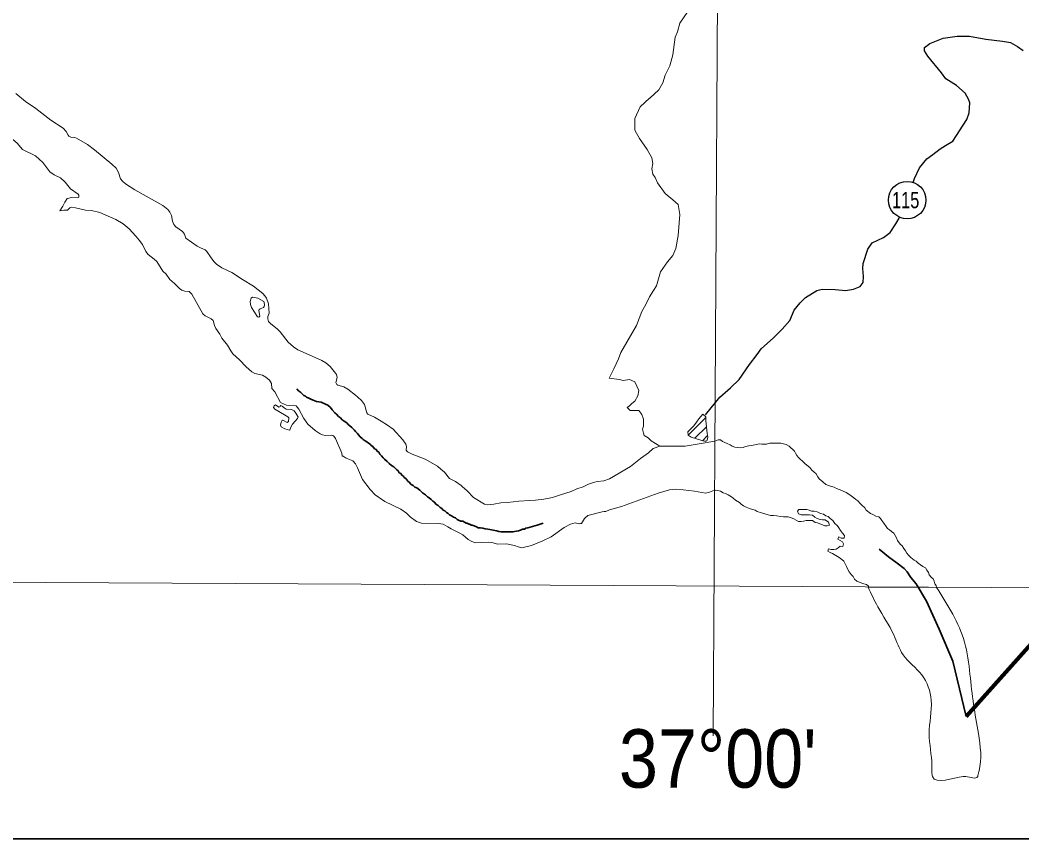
# Model space of a CAD drawing. Extents: x 553962 to 842807, y 8883888 to 9032388.
# Drawn here: x 604536 to 608828, y 8897728 to 8901238 of the extents above; entities that cross this region are included whole.
import ezdxf
from ezdxf.enums import TextEntityAlignment as Align

# ---------------------------------------------------------------- set-up
doc = ezdxf.new("R2010")
doc.units = 0
doc.header["$LTSCALE"] = 160
doc.linetypes.add('LONG_DASH_SHORT_DASH', pattern=[9.9, 6, -1.2, 1.5, -1.2])
doc.layers.add('6', color=7, linetype='Continuous', lineweight=13)

msp = doc.modelspace()

# ---------------------------------------------------------------- linework, layer by layer
at = {"layer": '6'}
for p, q in [((607398.2, 8899458.9), (607473.3, 8899534)), ((607427.1, 8899445.4), (607476, 8899494.2)), ((607458.9, 8899434.7), (607481.1, 8899456.9)), ((608462.4, 8898805.8), (608169.4, 8898807.8))]:
    msp.add_line(p, q, dxfattribs=at)
at = {"layer": '6', "lineweight": 35}
msp.add_lwpolyline([(576104.8, 8927170.9), (624533.7, 8927170.9), (624533.7, 8897728.1), (576104.8, 8897728.1)], close=True, dxfattribs=at)
at = {"layer": '6'}
for points in [[(607657.7, 8924743.3), (607574.2, 8909874.9), (607505, 8898170.6)], [(607518.6, 8901403.9), (607482.1, 8901370.7), (607412.3, 8901297.6), (607362.4, 8901224.5), (607352.5, 8901188), (607342.5, 8901164.7), (607332.5, 8901088.4), (607319.2, 8901041.9), (607299.3, 8901002), (607289.3, 8900968.8), (607272.7, 8900938.9), (607233.9, 8900903.3)], [(604517.3, 8900922.7), (604558.5, 8900888.9), (604603.8, 8900858.4), (604667, 8900809.4), (604720.7, 8900774.8), (604733.1, 8900760.8), (604741.5, 8900744.4), (604745.2, 8900740.3), (604753.2, 8900735.9), (604770.9, 8900734.2), (604776.8, 8900732.2), (604824.3, 8900704.6), (604854.7, 8900681.5), (604929.1, 8900620.1), (604947.7, 8900602.6), (604957.6, 8900585), (604966.3, 8900557.4), (604974.2, 8900547), (604987.4, 8900535.9), (605027.8, 8900510.6), (605147.2, 8900442.4), (605169.2, 8900426.4), (605178, 8900414.5), (605184.6, 8900400), (605189.5, 8900375.3), (605194.2, 8900361.7), (605203.3, 8900351.7), (605231.7, 8900331.2), (605239.8, 8900319.8), (605246.1, 8900303.3), (605294.8, 8900269.1), (605308.7, 8900261.3), (605318.4, 8900257.2)], [(607232.8, 8900902.4), (607193, 8900865.8), (607169.7, 8900816), (607169.7, 8900766.2), (607189.6, 8900729.7), (607222.9, 8900683.2), (607242.8, 8900646.7), (607246.1, 8900623.4), (607242.8, 8900600.2), (607246.1, 8900576.9), (607256.1, 8900563.6), (607266.1, 8900540.4), (607299.3, 8900493.9), (607332.5, 8900467.3), (607355.8, 8900447.4), (607362.4, 8900404.2), (607355.8, 8900314.6), (607345.8, 8900258.1), (607332.5, 8900228.2), (607309.3, 8900201.6), (607279.4, 8900158.5), (607262.7, 8900098.7), (607249.5, 8900078.8), (607232.8, 8900052.2), (607216.2, 8900019), (607199.6, 8899989.1), (607176.3, 8899929.3), (607109.9, 8899813.1), (607099.9, 8899786.5), (607080, 8899743.3), (607060, 8899703.5), (607103.2, 8899696.8), (607119.8, 8899693.5), (607146.4, 8899696.8), (607169.7, 8899686.9), (607186.3, 8899650.3), (607183, 8899627.1), (607169.7, 8899603.8), (607156.4, 8899593.9), (607146.4, 8899583.9), (607136.5, 8899577.3), (607149.8, 8899564), (607186.3, 8899564), (607199.6, 8899547.4), (607206.2, 8899527.4), (607206.2, 8899507.5), (607206.2, 8899497.6), (607202.9, 8899484.3), (607206.2, 8899467.7), (607209.6, 8899457.7), (607226.2, 8899447.8), (607239.5, 8899434.5), (607276, 8899411.2)], [(604545.7, 8900683.2), (604522.7, 8900710.9), (604449.6, 8900771.1), (604366, 8900847)], [(604745.3, 8900474.6), (604755.6, 8900477.1), (604782.2, 8900475.7), (604787.1, 8900478.4), (604787.9, 8900487.3), (604784.5, 8900492.2), (604752, 8900515.1), (604729.6, 8900542.8), (604709.4, 8900561), (604681.6, 8900575), (604663.6, 8900587.3), (604633.8, 8900627.5), (604602, 8900655.7), (604545.7, 8900683.2)], [(604729.9, 8900461.2), (604737.9, 8900472.8), (604745.3, 8900474.6)], [(604706.6, 8900419.8), (604719.1, 8900439.6), (604727.3, 8900457.6), (604729.9, 8900461.2), (604729.9, 8900461.2)], [(605045.3, 8900294.2), (605031, 8900312.3), (605003.2, 8900342.6), (604977.4, 8900365.2), (604945.5, 8900383.7), (604877.4, 8900413.4), (604842.3, 8900421.4), (604815.8, 8900423.5), (604773.8, 8900433.3), (604754.4, 8900435.3), (604749.3, 8900433), (604738.7, 8900423.7), (604723, 8900423.6), (604706.6, 8900419.8)], [(605438.8, 8899820.5), (605424.5, 8899844.7), (605400.3, 8899874.5), (605391.9, 8899891.1), (605374.3, 8899916.5), (605368.7, 8899929), (605362.7, 8899950.1), (605355.1, 8899957.3), (605329.3, 8899970.5), (605318.8, 8899978.5), (605271.5, 8900063.6), (605260.1, 8900073.8), (605241.3, 8900075.8), (605228.1, 8900080.5), (605218.7, 8900087.6), (605197.7, 8900109.2), (605177.8, 8900125.6), (605161.6, 8900148.5), (605147.3, 8900162.1), (605121.1, 8900202.5), (605110.9, 8900213.2), (605084.9, 8900233.7), (605074.1, 8900246.2), (605060.1, 8900275.4), (605045.3, 8900294.2)], [(605318.4, 8900257.2), (605328.1, 8900253.2), (605335.8, 8900246.2), (605350.9, 8900222.8), (605366.1, 8900202.7), (605377.3, 8900192.3), (605399.9, 8900175.6), (605442.3, 8900156.2), (605489.3, 8900126.6)], [(605489.3, 8900126.6), (605536.4, 8900097), (605576.3, 8900065.9), (605584, 8900055.8)], [(605584, 8900055.8), (605591.8, 8900045.6), (605599.5, 8900021.8), (605601.3, 8900001.9)], [(605601.3, 8900001.9), (605603.1, 8899982.1), (605597.9, 8899967.5), (605596.6, 8899957), (605600.2, 8899946.1), (605609.6, 8899935.7), (605637, 8899914.4), (605637, 8899914.4), (605649.8, 8899902), (605684.5, 8899857.5), (605707.9, 8899837.1), (605725.2, 8899825.1), (605748.8, 8899814.5)], [(605651.9, 8899599.2), (605627.2, 8899644.2), (605614.9, 8899659.3), (605613, 8899680), (605604.8, 8899694.2), (605588.8, 8899707.8), (605573.8, 8899716.3), (605540.9, 8899723.1), (605528.7, 8899729.8), (605504.9, 8899751.3), (605476.1, 8899781.6), (605446.9, 8899806.9), (605438.8, 8899820.5)], [(605748.8, 8899814.5), (605828.9, 8899778.6), (605845.6, 8899768.4), (605864.6, 8899753.2), (605875.9, 8899739.1)], [(605875.9, 8899739.1), (605887.1, 8899725), (605890.8, 8899718.1), (605893.6, 8899706.3), (605887.9, 8899684.9), (605892.5, 8899676.5), (605897.1, 8899672.9), (605922.3, 8899665.2), (605940.2, 8899656.1), (605972.7, 8899630.7), (605982.6, 8899621.7)], [(605982.6, 8899621.7), (605997.9, 8899607.7), (606011.1, 8899590.2), (606021.8, 8899555.1), (606026.3, 8899548.7), (606053.9, 8899535.2), (606082.6, 8899518.2)], [(605800.4, 8899478.3), (605768.7, 8899506.2), (605752.1, 8899530.8), (605730.5, 8899570.1), (605719.2, 8899583.9), (605706, 8899587.4), (605690.9, 8899586.3), (605677.8, 8899587.4), (605651.9, 8899599.2)], [(606082.6, 8899518.2), (606110.4, 8899501.7), (606133.8, 8899485.1), (606175, 8899438.1), (606188.2, 8899420.1), (606191.5, 8899410.3), (606189.5, 8899394.8), (606194.9, 8899386.7), (606215.6, 8899376.8), (606270.9, 8899356.2), (606324.1, 8899326.3), (606339, 8899313.3)], [(605886.8, 8899444.2), (605880.5, 8899454.1), (605875.6, 8899458), (605871.8, 8899459), (605843.6, 8899457.8), (605831.8, 8899459.6), (605821.4, 8899464.6), (605800.4, 8899478.3)], [(606167, 8899141.3), (606097.8, 8899173.8), (606057.4, 8899203.2), (606036.3, 8899225.7), (606003.4, 8899268.5), (605982, 8899319.3), (605972.7, 8899335.8), (605960.9, 8899348.2), (605932.8, 8899360.8), (605920.3, 8899368.7), (605916, 8899369.4), (605914.2, 8899381.2), (605886.8, 8899444.2)], [(606996.3, 8899256.7), (607009.1, 8899260.5), (607037.2, 8899263), (607061.2, 8899271.7), (607150.5, 8899324.7), (607193.7, 8899358.8), (607228.5, 8899383), (607248.7, 8899401.6), (607276, 8899411.2), (607305.9, 8899411.2), (607385.7, 8899411.2), (607445.5, 8899421.2), (607512.3, 8899432.5)], [(607512.3, 8899432.5), (607525.9, 8899438.3), (607537.1, 8899438.2), (607545.2, 8899432.1), (607555.3, 8899427.9), (607565.5, 8899422.8), (607577.6, 8899416.6), (607586.8, 8899411.4), (607597.9, 8899407.3), (607609.1, 8899406.2), (607621.3, 8899405.1), (607633.5, 8899406), (607643.7, 8899410), (607658, 8899413), (607671.2, 8899413.9), (607701.8, 8899420.9), (607713, 8899420.8), (607723.1, 8899420.7), (607734.3, 8899420.7), (607747.6, 8899424.6), (607757.7, 8899424.6), (607770, 8899424.5), (607783.2, 8899424.4), (607795.4, 8899424.3), (607806.6, 8899422.2), (607817.7, 8899418.1), (607830.9, 8899411.9), (607838, 8899404.7), (607846.1, 8899397.5), (607853.1, 8899390.3)], [(607853.1, 8899390.3), (607858.2, 8899381.2), (607863.2, 8899371.9), (607871.3, 8899363.7), (607878.3, 8899355.6), (607887.4, 8899347.3), (607899.6, 8899336.1), (607919.8, 8899319.6), (607927.8, 8899309.4), (607937, 8899302.2), (607946, 8899293), (607954.1, 8899280.7), (607959.1, 8899271.5), (607975.3, 8899258.1), (607987.4, 8899247.9), (607998.6, 8899242.7), (608011.8, 8899238.6), (608023, 8899235.4), (608033.1, 8899230.3), (608045.3, 8899226.1), (608056.4, 8899222), (608065.6, 8899217.8), (608075.7, 8899212.7), (608085.8, 8899205.5), (608097, 8899199.3), (608108.1, 8899190.1), (608116.2, 8899182.9), (608124.3, 8899176.7), (608135.4, 8899166.4), (608142.5, 8899159.3), (608154.6, 8899148), (608160.6, 8899137.8), (608178.8, 8899123.4), (608189, 8899119.2), (608202.2, 8899112), (608214.3, 8899108.9), (608222.4, 8899101.7), (608228.5, 8899092.5), (608236.5, 8899081.2), (608246.6, 8899067.9), (608252.7, 8899058.7), (608260.8, 8899052.6), (608269.9, 8899046.4), (608279, 8899038.2), (608291, 8899018.7), (608295, 8899007.5), (608306.1, 8898992.2), (608314.2, 8898985), (608322.3, 8898973.7), (608329.3, 8898963.5), (608335.3, 8898953.3), (608342.4, 8898945.1), (608352.5, 8898933.8), (608365.7, 8898923.5), (608374.8, 8898918.4), (608383.9, 8898910.2), (608393, 8898903), (608403.1, 8898895.8), (608414.2, 8898889.6), (608421.3, 8898880.4), (608427.3, 8898870.2), (608430.3, 8898859.9), (608439.4, 8898850.7), (608447.5, 8898843.5), (608451.5, 8898832.3)], [(606339, 8899313.3), (606353.8, 8899300.2), (606375.8, 8899273.6), (606401.3, 8899259.5), (606425.6, 8899243.5), (606430.3, 8899239.2)], [(606430.3, 8899239.2), (606451.1, 8899220.5), (606477.9, 8899191.6), (606526.1, 8899162.9), (606538.8, 8899160.4), (606552.3, 8899160.9), (606564.8, 8899163.4)], [(606850.9, 8899202.7), (606897.3, 8899217.3), (606921.3, 8899228.2), (606948.9, 8899237.7), (606970.8, 8899249.3), (606996.3, 8899256.7)], [(606743.5, 8899180.8), (606780.2, 8899185.1), (606817.4, 8899192.1), (606850.9, 8899202.7)], [(607510.3, 8899223.4), (607489.5, 8899213.8), (607472.3, 8899210.6), (607425.7, 8899218.6), (607376, 8899224.9), (607343.2, 8899226.9), (607318.7, 8899223.8), (607269.6, 8899209.6), (607112, 8899153.1), (607061.6, 8899139.4), (607044.9, 8899132.1), (607038.2, 8899131.2)], [(607965.2, 8899123.7), (607951, 8899129.9), (607937.8, 8899133.1), (607926.6, 8899133.2), (607916.5, 8899137.3), (607906.3, 8899140.4), (607892.1, 8899140.5), (607872.8, 8899140.6), (607866.6, 8899132.5), (607870.6, 8899122.3), (607882.8, 8899117.1), (607894, 8899117.1), (607904.2, 8899117), (607917.4, 8899116.9), (607930.6, 8899115.8), (607940.7, 8899107.6), (607950.8, 8899101.4), (607963, 8899097.3), (607974.2, 8899096.2), (607984.4, 8899096.1), (607999.6, 8899085.8), (608003.5, 8899073.6), (607993.3, 8899070.6), (607983.2, 8899070.6), (607973, 8899074.8), (607961.9, 8899078.9), (607952.7, 8899083.1), (607941.6, 8899084.2), (607930.4, 8899092.4), (607917.2, 8899093.5), (607903, 8899092.6), (607892.8, 8899089.6), (607881.6, 8899088.6), (607870.4, 8899088.7), (607861.3, 8899093.8), (607850.1, 8899100), (607840, 8899104.2), (607826.8, 8899108.3), (607816.6, 8899108.4), (607806.4, 8899108.4), (607793.2, 8899109.6), (607778, 8899112.7), (607763.7, 8899113.8), (607751.5, 8899113.9), (607741.4, 8899118), (607727.2, 8899122.2), (607712, 8899125.3), (607693.7, 8899131.6), (607684.6, 8899136.7), (607674.4, 8899139.9), (607661.2, 8899144), (607646, 8899150.2), (607634.8, 8899155.4), (607625.7, 8899163.6), (607617.7, 8899170.8), (607600.4, 8899180.1), (607591.3, 8899188.3), (607583.2, 8899194.4), (607569.1, 8899203.7), (607557.9, 8899208.9), (607547.8, 8899212), (607536.6, 8899218.2), (607525.4, 8899222.3), (607515.3, 8899222.4), (607510.3, 8899223.4)], [(606564.8, 8899163.4), (606594.8, 8899169.2), (606624, 8899170.2), (606673, 8899176.3), (606719.7, 8899178.1), (606743.5, 8899180.8)], [(606368.4, 8899065.7), (606348.9, 8899077), (606329, 8899080.2), (606255.6, 8899080.9), (606233.8, 8899088.8), (606207, 8899108.8), (606191.6, 8899125.1), (606167, 8899141.3)], [(607038.2, 8899131.2), (607030.1, 8899130.2), (606968.5, 8899113.9), (606953.5, 8899101.6), (606940.8, 8899080.5), (606936.9, 8899079.8)], [(608076.6, 8898895.8), (608072.6, 8898905), (608064.5, 8898918.3), (608056.4, 8898925.5), (608045.3, 8898934.7), (608031.1, 8898943), (608015.9, 8898952.2), (608006.8, 8898956.4), (607996.7, 8898961.5), (607999.8, 8898971.7), (608011, 8898968.6), (608022.1, 8898968.5), (608032.3, 8898969.5), (608040.5, 8898976.5), (608048.7, 8898982.6), (608060.9, 8898981.5), (608064, 8898992.7), (608059, 8899001.9), (608048.8, 8899007.1), (608039.7, 8899013.2), (608043.9, 8899022.4), (608054, 8899017.2), (608066.2, 8899017.1), (608067.3, 8899029.3), (608059.2, 8899038.6), (608051.2, 8899049.8), (608044.1, 8899061.1), (608036.1, 8899072.3), (608027, 8899080.5), (608017.9, 8899092.8), (608005.8, 8899102.1), (607997.7, 8899110.3), (607987.5, 8899113.4), (607977.4, 8899119.6), (607965.2, 8899123.7)], [(606669.7, 8898980.5), (606654.6, 8898985.8), (606620, 8898992.5), (606583.1, 8898992.2), (606556.5, 8898999.1), (606542.7, 8899000.4), (606485.3, 8898997.2), (606468.8, 8899003.8), (606455.3, 8899011.8), (606432, 8899031.1), (606419.7, 8899039.2), (606382.7, 8899057.4), (606368.4, 8899065.7)], [(606936.9, 8899079.8), (606931.9, 8899079.1), (606913.4, 8899083.4), (606894.4, 8899077.1), (606866.6, 8899063), (606810.7, 8899023.7), (606776, 8899005.8), (606726.3, 8898985.3), (606684.8, 8898975.2), (606669.7, 8898980.5)], [(577181.5, 8898943.8), (596544.3, 8898870.4), (623547.8, 8898727.2)], [(608169.4, 8898807.8), (608170.6, 8898811.7), (608162.5, 8898818.9), (608151.3, 8898821), (608142.2, 8898825.1), (608132.1, 8898829.2), (608120.9, 8898833.4), (608110.8, 8898841.6), (608104.8, 8898852.9), (608096.7, 8898862.1), (608087.6, 8898873.3), (608081.6, 8898882.6), (608076.6, 8898895.8)], [(608451.5, 8898832.3), (608454.5, 8898822.1), (608460.5, 8898813.9), (608462.4, 8898805.8), (608169.4, 8898807.8)]]:
    msp.add_lwpolyline(points, dxfattribs=at)
at = {"layer": '6', "lineweight": 25}
for points in [[(608362.5, 8900541.9), (608368.2, 8900558.4), (608389.8, 8900605.2), (608420.5, 8900642.9), (608446, 8900662.2), (608477.7, 8900686.6), (608500.2, 8900699.8), (608531.8, 8900719.1), (608592.3, 8900811.7), (608601.6, 8900840.2), (608604.8, 8900883), (608599.7, 8900899.3), (608584.6, 8900924.8), (608548, 8900957.4), (608502.2, 8900986.1), (608484, 8901011.6), (608424.2, 8901083), (608411, 8901106.4), (608410, 8901120.7), (608433.5, 8901137), (608490.7, 8901160.3), (608550.8, 8901168.3), (608602.8, 8901168.2), (608674, 8901155.9), (608745.3, 8901147.6), (608778.9, 8901141.4), (608808.4, 8901124), (608833.8, 8901107.7)], [(607472.2, 8899545.8), (607534.4, 8899621.6), (607579.4, 8899661.2), (607616.2, 8899696.8), (607661.2, 8899761.9), (607694, 8899804.7), (607711.4, 8899829.1), (607763.6, 8899875.9), (607801.4, 8899912.5), (607833.1, 8899950.1), (607852.6, 8899993.9), (607877.2, 8900026.4), (607900.7, 8900048.8), (607948.7, 8900079.3), (607972.2, 8900084.3), (608027.2, 8900083.2), (608072, 8900078.1), (608106.7, 8900084.1), (608135.2, 8900096.3), (608147.5, 8900113.6), (608148.6, 8900139), (608146.7, 8900173.7), (608147.8, 8900194.1), (608168.4, 8900255.2), (608186.9, 8900283.6), (608234.8, 8900306), (608263.4, 8900327.3), (608288, 8900363.9), (608301.4, 8900388.4), (608303.7, 8900393.1)]]:
    msp.add_lwpolyline(points, dxfattribs=at)
at = {"layer": '6'}
for points in [[(605578, 8900006.4), (605581.1, 8900009.7), (605583.1, 8900017.2), (605581.8, 8900027.9), (605579.6, 8900031.9), (605553.8, 8900045.2), (605540.6, 8900049.4), (605532.2, 8900049.6), (605526.5, 8900045.7), (605520.9, 8900031.3), (605522.3, 8900018.3), (605527.3, 8900006.6), (605552.8, 8899966.1), (605559, 8899963.9), (605562.7, 8899968.7), (605558.6, 8899992.7), (605559.4, 8899996.8), (605563.9, 8900000.6)], [(605726.5, 8899537.9), (605724, 8899530.6), (605714.4, 8899518.2), (605703, 8899506.1), (605697.8, 8899496.6), (605691.8, 8899481.5), (605690, 8899479.8), (605670.7, 8899486.1), (605654.2, 8899494.3), (605651.4, 8899501.1), (605654.2, 8899514.3), (605658.7, 8899522.5), (605659.8, 8899523), (605664.4, 8899521.9), (605680, 8899513.5), (605686.4, 8899518), (605687.1, 8899532.4), (605682.6, 8899537.5), (605669, 8899546.2), (605627.1, 8899569.7), (605621, 8899577.3), (605624.1, 8899584.8), (605629.5, 8899588.5), (605644.9, 8899579.4), (605648.7, 8899580.6), (605650.3, 8899583.7), (605653.3, 8899585.6), (605658.1, 8899583.4), (605667.7, 8899575.2), (605676.3, 8899570.6), (605698.8, 8899568.8), (605709.7, 8899562.8), (605717.5, 8899553.2), (605726.3, 8899538.9)], [(607460.5, 8899548.4), (607473.4, 8899537.4), (607473.1, 8899520.7), (607479, 8899466.9), (607482.5, 8899450.2), (607481.5, 8899443.7), (607477.8, 8899435.1), (607475, 8899432.4), (607467.5, 8899432.5), (607456.8, 8899435.3), (607411.1, 8899450.8), (607397.8, 8899459.1), (607396.2, 8899472.7), (607398.9, 8899476.5), (607421.7, 8899498.1), (607434.4, 8899514.6), (607443.2, 8899529)]]:
    msp.add_lwpolyline(points, close=True, dxfattribs=at)
at = {"layer": '6', "lineweight": 90}
msp.add_lwpolyline([(608589.7, 8898253.2), (609486.3, 8899256.3), (611805.4, 8899391.2), (611936.3, 8899690.5)], dxfattribs=at)
at = {"layer": '6', "linetype": 'LONG_DASH_SHORT_DASH', "lineweight": 35}
for points in [[(605956.8, 8899491.3), (605948.6, 8899499.4), (605941.5, 8899504.1), (605935.9, 8899511.2), (605923.7, 8899519.4), (605916, 8899524), (605907.9, 8899532.7), (605899.8, 8899538.3), (605891.6, 8899548.5), (605884.5, 8899554.7), (605873.3, 8899567.4), (605865.1, 8899577.7), (605855, 8899586.9), (605844.3, 8899592), (605825.4, 8899599.7), (605805.6, 8899603.2), (605791.3, 8899609.4), (605781.7, 8899613.5), (605773, 8899617.5), (605763.3, 8899621.6), (605758.2, 8899625.7), (605751.6, 8899628.8), (605744.5, 8899635.4), (605736.9, 8899643.1), (605728.7, 8899648.2), (605721.2, 8899657.3)], [(606202.1, 8899256.6), (606197.1, 8899261.7), (606188.4, 8899272.5), (606181.8, 8899277.1), (606178.2, 8899283.7), (606171.1, 8899287.3), (606167, 8899293.9), (606159.4, 8899298), (606155.3, 8899306.2), (606148.2, 8899311.3), (606137, 8899323.6), (606127.3, 8899328.2), (606117.1, 8899337.9), (606108, 8899345.6), (606097.3, 8899355.8), (606091.2, 8899361.4), (606084, 8899370.1), (606076.9, 8899377.8), (606072.3, 8899385.4), (606065.2, 8899389.5), (606061.1, 8899397.2), (606054, 8899400.8), (606046.9, 8899410.5), (606039.7, 8899414.1), (606035.2, 8899420.2), (606028, 8899423.8), (606020.9, 8899430.4), (606013.8, 8899434), (606005.6, 8899440.7), (606001.1, 8899444.8), (605993.4, 8899450.9), (605985.8, 8899460.1), (605980.7, 8899465.7), (605973.1, 8899474.9), (605968.5, 8899480), (605961.3, 8899486.7), (605956.8, 8899491.3)], [(606696.3, 8899056.2), (606688.7, 8899055.7), (606679.1, 8899051.6), (606671.4, 8899049.1), (606662.8, 8899047.5), (606654.6, 8899046), (606649, 8899045), (606641.9, 8899044), (606630.2, 8899044), (606622.6, 8899044), (606614.4, 8899044), (606609.8, 8899044), (606602.2, 8899044.5), (606596.6, 8899045), (606586.9, 8899046.5), (606578.3, 8899048.1), (606570.1, 8899049.6), (606562.5, 8899051.1), (606554.9, 8899052.7), (606548.3, 8899054.2), (606540.1, 8899055.7), (606528.4, 8899057.2), (606517.7, 8899060.3), (606508.1, 8899061.8), (606498.9, 8899061.8), (606490.8, 8899065.9), (606481.1, 8899069.5), (606472.9, 8899072.6), (606468.9, 8899073.6), (606462.8, 8899076.7), (606458.7, 8899077.7), (606451.1, 8899081.3), (606446.5, 8899082.3), (606439.8, 8899086.4), (606432.2, 8899090), (606423.6, 8899090.5), (606414.4, 8899094.1), (606408.3, 8899097.6), (606400.7, 8899103.8), (606392.5, 8899106.8), (606384.4, 8899113.5), (606375.7, 8899116.6), (606370.1, 8899122.7), (606362.5, 8899127.8), (606355.4, 8899133.9), (606347.7, 8899138), (606342.6, 8899144.7), (606336, 8899148.8), (606326.8, 8899156.9), (606316.7, 8899162.6), (606311.6, 8899171.8), (606304, 8899176.4), (606297.3, 8899183.5), (606288.2, 8899190.7), (606281.6, 8899194.8), (606273.4, 8899202.4), (606268.3, 8899205.5), (606260.2, 8899212.2), (606255.6, 8899215.2), (606248, 8899222.9), (606236.2, 8899232.6), (606227.6, 8899235.2), (606219.4, 8899243.3), (606211.3, 8899247.4), (606202.1, 8899256.6)], [(606776.9, 8899082.3), (606776.7, 8899082.3), (606768.6, 8899079.2), (606759.4, 8899076.2), (606750.8, 8899073.6), (606731.5, 8899067.5), (606720.8, 8899063.9), (606711.6, 8899061.3), (606701.9, 8899060.3), (606696.3, 8899056.2)], [(608589.7, 8898253.2), (608531.8, 8898489.6), (608473.8, 8898626.9), (608419.7, 8898746.8), (608375.2, 8898822.2), (608352, 8898849.2), (608336.5, 8898872.3), (608323.3, 8898886.6), (608292.9, 8898910.1), (608256.3, 8898937.7), (608216.7, 8898970.6)]]:
    msp.add_lwpolyline(points, dxfattribs=at)
at = {"layer": '6', "lineweight": 25}
msp.add_circle((608336.3, 8900466.1), 80.3, dxfattribs=at)
at = {"layer": '6'}
msp.add_spline([(608169.4, 8898807.8), (608210, 8898723.6), (608278.8, 8898603.2), (608318.9, 8898517.3), (608399.1, 8898431.3), (608439.2, 8898322.4), (608430.6, 8898179.2), (608442.1, 8898044.5), (608442.1, 8898015.4), (608445, 8897995.8), (608576.8, 8897995.8), (608588.2, 8897995.8), (608638.5, 8897995.8), (608640.5, 8898005.2), (608644.2, 8898020.1), (608641.5, 8898180.1), (608620.8, 8898304.5), (608605.4, 8898434.2), (608582.5, 8898571.7), (608462.4, 8898805.8)], degree=3, dxfattribs=at)

# ---------------------------------------------------------------- texts
for s, height, width, p in [('115', 70, 0.75, (608329.9, 8900431.4)), ("37°00'", 250, 0.9, (607524.9, 8897948.1))]:
    msp.add_text(s, height=height, dxfattribs=dict(at, width=width)).set_placement(p, align=Align.CENTER)

doc.saveas('drawing.dxf')
